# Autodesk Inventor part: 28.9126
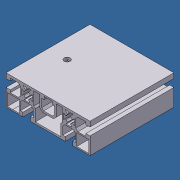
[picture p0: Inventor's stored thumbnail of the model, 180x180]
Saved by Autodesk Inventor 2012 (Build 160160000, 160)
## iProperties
Created: 2007-06
Part Number: 28.9126
Material: Aluminum-6061
Document SubType Name: Modeling
Designer: Andy Moles
Density: 2.71 g/cm^3
Description: L = 3.543", MILL TO 28.9126
Stock Number: 20.1066 PROFILE 90X32
Vendor: F
Author: Andy Moles
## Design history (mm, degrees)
sketch "Sketch1"
  geometry: L1 (4.25, 7.901)-(4.25, 5) reference; L2 (6.8, 5)-(6.8, -3.8) reference; L3 (6.8, -3.8)-(4.8, -5.8) reference; L4 (4.8, -5.8)-(-4.8, -5.8) reference; L5 (-4.8, -5.8)-(-6.8, -3.8) reference; L6 (-6.8, -3.8)-(-6.8, 5) reference; L7 (-4.25, 5)-(-4.25, 7.901) reference; L8 (-45, 9.5)-(45, 9.5) reference; L9 (-45, 4.1)-(-40.5, 4.1) reference; L10 (-40.5, 6.8)-(-32, 6.8) reference; L11 (-32, 6.8)-(-29.7, 4.5) reference; L12 (-29.7, 4.5)-(-29.7, -4.5) reference; L13 (-29.7, -4.5)-(-32, -6.8) reference; L14 (-32, -6.8)-(-40.5, -6.8) reference; L15 (-40.5, -4.1)-(-45, -4.1) reference; L16 (-45, -22.5)-(-45, -4.4) reference; L17 (45, -4.1)-(40.5, -4.1) reference; L18 (40.5, -6.8)-(32, -6.8) reference; L19 (32, -6.8)-(29.7, -4.5) reference; L20 (29.7, -4.5)-(29.7, 4.5) reference; L21 (29.7, 4.5)-(32, 6.8) reference; L22 (32, 6.8)-(40.5, 6.8) reference; L23 (40.5, 4.1)-(45, 4.1) reference; L24 (-43.6, -21.1)-(-43.6, -8.2) reference; L25 (-43.6, -13.915)-(-43.6, -9.2) reference; L26 (-43.6, -8.2)-(-36.415, -8.2) reference; L27 (-36.415, -8.2)-(-30.7, -8.2) reference; L28 (-30.7, -8.2)-(-30.7, -21.1) reference; L29 (-30.7, -21.1)-(-37.885, -21.1) reference; L30 (-37.885, -21.1)-(-43.6, -21.1) reference; L31 (30.7, -21.1)-(30.7, -8.2) reference; L32 (30.7, -8.2)-(43.6, -8.2) reference; L33 (43.6, -8.2)-(43.6, -21.1) reference; L34 (43.6, -21.1)-(30.7, -21.1) reference; L35 (-28.3, -2.813)-(-28.3, 2.813) reference; L36 (-27.788, 3.025)-(-26.269, 1.506) reference; L37 (-24.006, 3.769)-(-26.725, 6.488) reference; L38 (-26.513, 7)-(-23.753, 7) reference; L39 (-23.464, 6.778)-(-23.08, 5.345) reference; L40 (-21.92, 5.345)-(-21.536, 6.778) reference; L41 (-21.247, 7)-(-18.487, 7) reference; L42 (-18.275, 6.488)-(-20.994, 3.769) reference; L43 (-18.731, 1.506)-(-17.212, 3.025) reference; L44 (-16.7, 2.813)-(-16.7, -2.813) reference; L45 (-17.212, -3.025)-(-18.731, -1.506) reference; L46 (-20.994, -3.769)-(-19.475, -5.288) reference; L47 (-19.687, -5.8)-(-25.313, -5.8) reference; L48 (-25.525, -5.288)-(-24.006, -3.769) reference; L49 (-26.269, -1.506)-(-27.788, -3.025) reference; L50 (16.7, -2.813)-(16.7, 2.813) reference; L51 (17.212, 3.025)-(18.731, 1.506) reference; L52 (20.994, 3.769)-(18.275, 6.488) reference; L53 (18.487, 7)-(21.247, 7) reference; L54 (21.536, 6.778)-(21.92, 5.345) reference; L55 (23.08, 5.345)-(23.464, 6.778) reference; L56 (23.753, 7)-(26.513, 7) reference; L57 (26.725, 6.488)-(24.006, 3.769) reference; L58 (26.269, 1.506)-(27.788, 3.025) reference; L59 (28.3, 2.813)-(28.3, -2.813) reference; L60 (27.788, -3.025)-(26.269, -1.506) reference; L61 (24.006, -3.769)-(25.525, -5.288) reference; L62 (25.313, -5.8)-(19.687, -5.8) reference; L63 (19.475, -5.288)-(20.994, -3.769) reference; L64 (18.731, -1.506)-(17.212, -3.025) reference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; A1 r 0.3 centre (-28, 2.813) between (-27.788, 3.025) and (-28.3, 2.813) reference; A2 r 0.3 centre (-26.057, 1.718) between (-26.269, 1.506) and (-25.787, 1.588) reference; A3 r 3.65 centre (-22.5, 0) between (-24.088, 3.287) and (-25.787, 1.588) reference; A4 r 0.3 centre (-24.218, 3.557) between (-24.088, 3.287) and (-24.006, 3.769) reference; A5 r 0.3 centre (-26.513, 6.7) between (-26.513, 7) and (-26.725, 6.488) reference; A6 r 0.3 centre (-23.753, 6.7) between (-23.464, 6.778) and (-23.753, 7) reference; A7 r 0.6 centre (-22.5, 5.5) between (-23.08, 5.345) and (-21.92, 5.345) reference; A8 r 0.3 centre (-21.247, 6.7) between (-21.247, 7) and (-21.536, 6.778) reference; A9 r 0.3 centre (-18.487, 6.7) between (-18.275, 6.488) and (-18.487, 7) reference; A10 r 0.3 centre (-20.782, 3.557) between (-20.994, 3.769) and (-20.912, 3.287) reference; A11 r 3.65 centre (-22.5, 0) between (-19.213, 1.588) and (-20.912, 3.287) reference; A12 r 0.3 centre (-18.943, 1.718) between (-19.213, 1.588) and (-18.731, 1.506) reference; A13 r 0.3 centre (-17, 2.813) between (-16.7, 2.813) and (-17.212, 3.025) reference; A14 r 0.3 centre (-17, -2.813) between (-17.212, -3.025) and (-16.7, -2.813) reference; A15 r 0.3 centre (-18.943, -1.718) between (-18.731, -1.506) and (-19.213, -1.588) reference; A16 r 3.65 centre (-22.5, 0) between (-20.912, -3.287) and (-19.213, -1.588) reference; A17 r 0.3 centre (-20.782, -3.557) between (-20.912, -3.287) and (-20.994, -3.769) reference; A18 r 0.3 centre (-19.687, -5.5) between (-19.687, -5.8) and (-19.475, -5.288) reference; A19 r 0.3 centre (-25.313, -5.5) between (-25.525, -5.288) and (-25.313, -5.8) reference; A20 r 0.3 centre (-24.218, -3.557) between (-24.006, -3.769) and (-24.088, -3.287) reference; A21 r 3.65 centre (-22.5, 0) between (-25.787, -1.588) and (-24.088, -3.287) reference; A22 r 0.3 centre (-26.057, -1.718) between (-25.787, -1.588) and (-26.269, -1.506) reference; A23 r 0.3 centre (-28, -2.813) between (-28.3, -2.813) and (-27.788, -3.025) reference; A24 r 0.3 centre (17, 2.813) between (17.212, 3.025) and (16.7, 2.813) reference; A25 r 0.3 centre (18.943, 1.718) between (18.731, 1.506) and (19.213, 1.588) reference; A26 r 3.65 centre (22.5, 0) between (20.912, 3.287) and (19.213, 1.588) reference; A27 r 0.3 centre (20.782, 3.557) between (20.912, 3.287) and (20.994, 3.769) reference; A28 r 0.3 centre (18.487, 6.7) between (18.487, 7) and (18.275, 6.488) reference; A29 r 0.3 centre (21.247, 6.7) between (21.536, 6.778) and (21.247, 7) reference; A30 r 0.6 centre (22.5, 5.5) between (21.92, 5.345) and (23.08, 5.345) reference; A31 r 0.3 centre (23.753, 6.7) between (23.753, 7) and (23.464, 6.778) reference; A32 r 0.3 centre (26.513, 6.7) between (26.725, 6.488) and (26.513, 7) reference; A33 r 0.3 centre (24.218, 3.557) between (24.006, 3.769) and (24.088, 3.287) reference; A34 r 3.65 centre (22.5, 0) between (25.787, 1.588) and (24.088, 3.287) reference; A35 r 0.3 centre (26.057, 1.718) between (25.787, 1.588) and (26.269, 1.506) reference; A36 r 0.3 centre (28, 2.813) between (28.3, 2.813) and (27.788, 3.025) reference; A37 r 0.3 centre (28, -2.813) between (27.788, -3.025) and (28.3, -2.813) reference; A38 r 0.3 centre (26.057, -1.718) between (26.269, -1.506) and (25.787, -1.588) reference; A39 r 3.65 centre (22.5, 0) between (24.088, -3.287) and (25.787, -1.588) reference; A40 r 0.3 centre (24.218, -3.557) between (24.088, -3.287) and (24.006, -3.769) reference; A41 r 0.3 centre (25.313, -5.5) between (25.313, -5.8) and (25.525, -5.288) reference; A42 r 0.3 centre (19.687, -5.5) between (19.475, -5.288) and (19.687, -5.8) reference; A43 r 0.3 centre (20.782, -3.557) between (20.994, -3.769) and (20.912, -3.287) reference; A44 r 3.65 centre (22.5, 0) between (19.213, -1.588) and (20.912, -3.287) reference; A45 r 0.3 centre (18.943, -1.718) between (19.213, -1.588) and (18.731, -1.506) reference; A46 r 0.3 centre (17, -2.813) between (16.7, -2.813) and (17.212, -3.025) reference
  constraints: 226 end point, 92 point on circle, 46 centre point, 31 horizontal, 24 vertical, 3 point on line, 1 perpendicular, 309 other
extrude "Extrusion1" new body sketch "Sketch1" stored distance "d18" = 90; taper "d19" = 0 deg
hole "Hole1" diameter "d22" = 6.5; stored, may be unused: countersink angle "d26" = 90 deg, drill point angle "d28" = 118 deg; dims "d20" = 45, "d21" = 20.5, "d23" = 6, "d24" = 4, "d25" = 2, "d27" = 8
body "Solid1"
other parameters: "d14" = 32
